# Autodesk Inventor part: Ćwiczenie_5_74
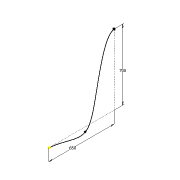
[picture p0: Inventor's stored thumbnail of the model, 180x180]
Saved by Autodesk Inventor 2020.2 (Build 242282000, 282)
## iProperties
Created: 2005-08
Part Number: Ćwiczenie_5_74
Document SubType Name: Modeling
Designer: F.Stasiak
Manufacturer: Standard
Standards Organization: Custom
Density: 1 g/cm^3
Material: Ogólny
Appearance: Domyślna
Manager: www.cadconsulting.pl
Company: Fabian Stasiak CAD Consulting
Author: F.Stasiak
Subject: Zbiór ćwiczeń. Autodesk Inventor 2020. Kurs podstawowy
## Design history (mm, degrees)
sketch "Szkic2"
  geometry: L1 (0, 0)-(650, 0); L2 (650, 0)-(650, 700); L3 (124.473, 0)-(-124.473, 0) reference; L4 (712.237, 700)-(587.763, 700); L5 (414.537, -13.762)-(304.942, -72.775) reference; A1 r 246.052 centre (0, -246.052) between (111.07, -26.495) and (-111.07, -26.495); A2 r 43.832 centre (650, 656.168) between (685.836, 681.407) and (614.164, 681.407); A3 r 85.312 centre (319.293, 31.846) between (307.699, -52.675) and (396.238, -5); 1 further point
  constraints: 10 end point, 6 midpoint, 4 horizontal, 3 centre point, 3 point on circle, 2 perpendicular, 1 collinear, 9 other
  dimensions: "d0" = 650 distance of L1.start L1.end; "d2" = 700 distance of L1.end L2.end; "d3" = 5 dimension on L4.start L4.end; "d4" = 10 dimension on L3.start L3.end; "d5" = 5 dimension on L5.start L5.end
node "Korpusy bryłowe"
node "Korpusy powierzchniowe"
